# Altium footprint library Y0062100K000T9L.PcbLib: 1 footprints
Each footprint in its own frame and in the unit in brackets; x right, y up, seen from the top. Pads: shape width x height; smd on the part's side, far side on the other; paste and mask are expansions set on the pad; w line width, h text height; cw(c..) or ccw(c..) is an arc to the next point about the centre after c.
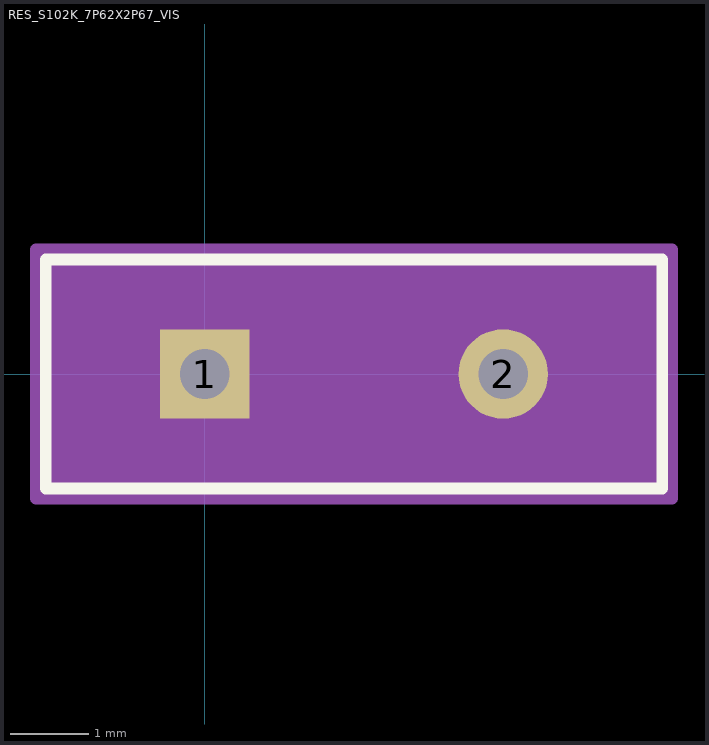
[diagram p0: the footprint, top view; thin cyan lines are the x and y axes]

## RES_S102K_7P62X2P67_VIS [mil]
pads (2):
  rect 45x45 hole 25 paste-22.5 mask+0: 1(0,0)
  round 45 hole 25 paste-22.5 mask+0: 2(150,0)
Top Overlay:
  lines w6: -80,-57.5 230,-57.5 230,57.5 -80,57.5 -80,-57.5
  text ".Designator" at -62.5,-25 h50
Mechanical 13:
  lines w1: -75,-52.5 225,-52.5 225,52.5 -75,52.5 -75,-52.5
  text ".Designator" at -62.5,-25 h50
Mechanical 15:
  region: 235,-62.5 -85,-62.5 -85,62.5 235,62.5
  lines w6: -85,-62.5 -85,62.5 235,62.5 235,-62.5 -85,-62.5
3D body "RES_S102K_7P62X2P67_VIS.step": height 335.98, standoff -180, extent -75,-52.52 225,52.52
